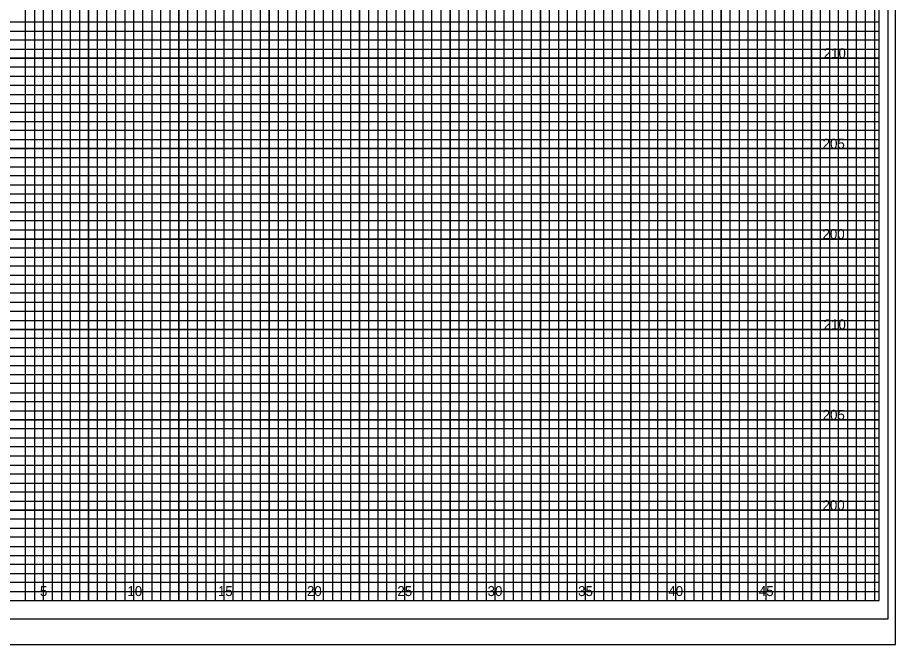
# Model space of a CAD drawing. Extents: x -4 to 103, y -2 to 209.
# Drawn here: x 54.82 to 103.4, y 68.4 to 103.08 of the extents above; entities that cross this region are included whole.
import ezdxf

# ---------------------------------------------------------------- set-up
doc = ezdxf.new("R2010")
doc.units = 0
for name, color, linetype in [('Old_Level_10', 7, 'Continuous'), ('Old_Level_16', 7, 'Continuous'), ('Old_Level_17', 7, 'Continuous'), ('Old_Level_3', 7, 'Continuous'), ('Old_Level_5', 7, 'Continuous'), ('Old_Level_6', 7, 'Continuous'), ('Old_Level_8', 7, 'Continuous'), ('Prop Dimension', 7, 'Continuous'), ('Typical Curb CELL', 7, 'Continuous')]:
    doc.layers.add(name, color=color, linetype=linetype)

msp = doc.modelspace()

# ---------------------------------------------------------------- linework, layer by layer
at = {"layer": 'Old_Level_10'}
for p, q in [((56.25, 70.825), (56.25, 135.825)), ((58.75, 70.825), (58.75, 135.825)), ((61.25, 70.825), (61.25, 135.825)), ((63.75, 70.825), (63.75, 135.825)), ((66.25, 70.825), (66.25, 135.825)), ((68.75, 70.825), (68.75, 135.825)), ((71.25, 70.825), (71.25, 135.825)), ((73.75, 70.825), (73.75, 135.825)), ((91.25, 70.825), (91.25, 134.25)), ((93.75, 70.825), (93.75, 134.25)), ((96.25, 70.825), (96.25, 134.25)), ((98.75, 70.825), (98.75, 134.25)), ((101.25, 70.825), (101.25, 134.25)), ((76.25, 70.825), (76.25, 132.825)), ((78.75, 70.825), (78.75, 132.825)), ((81.25, 70.825), (81.25, 132.825)), ((83.75, 70.825), (83.75, 132.825)), ((86.25, 70.825), (86.25, 132.825)), ((88.75, 70.825), (88.75, 132.825)), ((0, 100.825), (102.5, 100.825)), ((0, 98.325), (102.5, 98.325)), ((0, 95.825), (102.5, 95.825)), ((0, 93.325), (102.5, 93.325)), ((0, 90.825), (102.5, 90.825)), ((0, 88.325), (102.5, 88.325)), ((0, 85.825), (102.5, 85.825)), ((0, 83.325), (102.5, 83.325)), ((0, 80.825), (102.5, 80.825)), ((0, 78.325), (102.5, 78.325)), ((0, 75.825), (102.5, 75.825)), ((0, 73.325), (102.5, 73.325))]:
    msp.add_line(p, q, dxfattribs=at)
at = {"layer": 'Old_Level_17'}
for points in [[(54.75, 70.825), (55.25, 70.825), (55.25, 135.825)], [(55.75, 135.825), (55.75, 70.825), (56.75, 70.825), (56.75, 135.825)], [(57.25, 135.825), (57.25, 70.825), (57.75, 70.825), (57.75, 135.825)], [(58.25, 135.825), (58.25, 70.825), (59.25, 70.825), (59.25, 135.825)], [(59.75, 135.825), (59.75, 70.825), (60.25, 70.825), (60.25, 135.825)], [(60.75, 135.825), (60.75, 70.825), (61.75, 70.825), (61.75, 135.825)], [(62.25, 135.825), (62.25, 70.825), (62.75, 70.825), (62.75, 135.825)], [(63.25, 135.825), (63.25, 70.825), (64.25, 70.825), (64.25, 135.825)], [(64.75, 135.825), (64.75, 70.825), (65.25, 70.825), (65.25, 135.825)], [(65.75, 135.825), (65.75, 70.825), (66.75, 70.825), (66.75, 135.825)], [(67.25, 135.825), (67.25, 70.825), (67.75, 70.825), (67.75, 135.825)], [(68.25, 135.825), (68.25, 70.825), (69.25, 70.825), (69.25, 135.825)], [(69.75, 135.825), (69.75, 70.825), (70.25, 70.825), (70.25, 135.825)], [(70.75, 135.825), (70.75, 70.825), (71.75, 70.825), (71.75, 135.825)], [(72.25, 135.825), (72.25, 70.825), (72.75, 70.825), (72.75, 135.825)], [(73.25, 135.825), (73.25, 70.825), (74.25, 70.825), (74.25, 132.825)], [(89.75, 132.825), (89.75, 70.825), (90.25, 70.825), (90.25, 134.25)], [(90.75, 134.25), (90.75, 70.825), (91.75, 70.825), (91.75, 134.25)], [(92.25, 134.25), (92.25, 70.825), (92.75, 70.825), (92.75, 134.25)], [(93.25, 134.25), (93.25, 70.825), (94.25, 70.825), (94.25, 134.25)], [(94.75, 134.25), (94.75, 70.825), (95.25, 70.825), (95.25, 134.25)], [(95.75, 134.25), (95.75, 70.825), (96.75, 70.825), (96.75, 134.25)], [(97.25, 134.25), (97.25, 70.825), (97.75, 70.825), (97.75, 134.25)], [(98.25, 134.25), (98.25, 70.825), (99.25, 70.825), (99.25, 134.25)], [(99.75, 134.25), (99.75, 70.825), (100.25, 70.825), (100.25, 134.25)], [(100.25, 134.25), (100.75, 134.25), (100.75, 70.825), (101.75, 70.825), (101.75, 134.25), (102.25, 134.25), (102.25, 70.825)], [(74.75, 132.825), (74.75, 70.825), (75.25, 70.825), (75.25, 132.825)], [(75.75, 132.825), (75.75, 70.825), (76.75, 70.825), (76.75, 132.825)], [(77.25, 132.825), (77.25, 70.825), (77.75, 70.825), (77.75, 132.825)], [(78.25, 132.825), (78.25, 70.825), (79.25, 70.825), (79.25, 132.825)], [(79.75, 132.825), (79.75, 70.825), (80.25, 70.825), (80.25, 132.825)], [(80.75, 132.825), (80.75, 70.825), (81.75, 70.825), (81.75, 132.825)], [(82.25, 132.825), (82.25, 70.825), (82.75, 70.825), (82.75, 132.825)], [(83.25, 132.825), (83.25, 70.825), (84.25, 70.825), (84.25, 132.825)], [(84.75, 132.825), (84.75, 70.825), (85.25, 70.825), (85.25, 132.825)], [(85.75, 132.825), (85.75, 70.825), (86.75, 70.825), (86.75, 132.825)], [(87.25, 132.825), (87.25, 70.825), (87.75, 70.825), (87.75, 132.825)], [(88.25, 132.825), (88.25, 70.825), (89.25, 70.825), (89.25, 132.825)], [(0, 102.325), (102.5, 102.325), (102.5, 102.825), (0, 102.825)], [(0, 101.325), (102.5, 101.325), (102.5, 101.825), (0, 101.825)], [(0, 99.825), (102.5, 99.825), (102.5, 100.325), (0, 100.325)], [(0, 98.825), (102.5, 98.825), (102.5, 99.325), (0, 99.325)], [(0, 97.325), (102.5, 97.325), (102.5, 97.825), (0, 97.825)], [(0, 96.325), (102.5, 96.325), (102.5, 96.825), (0, 96.825)], [(0, 94.825), (102.5, 94.825), (102.5, 95.325), (0, 95.325)], [(0, 93.825), (102.5, 93.825), (102.5, 94.325), (0, 94.325)], [(0, 92.325), (102.5, 92.325), (102.5, 92.825), (0, 92.825)], [(0, 91.325), (102.5, 91.325), (102.5, 91.825), (0, 91.825)], [(0, 89.825), (102.5, 89.825), (102.5, 90.325), (0, 90.325)], [(0, 88.825), (102.5, 88.825), (102.5, 89.325), (0, 89.325)], [(0, 87.325), (102.5, 87.325), (102.5, 87.825), (0, 87.825)], [(0, 86.325), (102.5, 86.325), (102.5, 86.825), (0, 86.825)], [(0, 84.825), (102.5, 84.825), (102.5, 85.325), (0, 85.325)], [(0, 83.825), (102.5, 83.825), (102.5, 84.325), (0, 84.325)], [(0, 82.325), (102.5, 82.325), (102.5, 82.825), (0, 82.825)], [(0, 81.325), (102.5, 81.325), (102.5, 81.825), (0, 81.825)], [(0, 79.825), (102.5, 79.825), (102.5, 80.325), (0, 80.325)], [(0, 78.825), (102.5, 78.825), (102.5, 79.325), (0, 79.325)], [(0, 77.325), (102.5, 77.325), (102.5, 77.825), (0, 77.825)], [(0, 76.325), (102.5, 76.325), (102.5, 76.825), (0, 76.825)], [(0, 74.825), (102.5, 74.825), (102.5, 75.325), (0, 75.325)], [(0, 73.825), (102.5, 73.825), (102.5, 74.325), (0, 74.325)], [(0, 72.325), (102.5, 72.325), (102.5, 72.825), (0, 72.825)], [(0, 71.325), (102.5, 71.325), (102.5, 71.825), (0, 71.825)]]:
    msp.add_lwpolyline(points, dxfattribs=at)
at = {"layer": 'Old_Level_3'}
msp.add_line((-3.5, 68.4), (103.4, 68.4), dxfattribs=at)
at = {"layer": 'Old_Level_5'}
msp.add_lwpolyline([(103.4, 138.225), (-3.5, 138.225), (-3.5, 68.4), (103.4, 68.4)], close=True, dxfattribs=at)
at = {"layer": 'Old_Level_6'}
msp.add_lwpolyline([(102.5, 135.825), (0, 135.825), (0, 70.825), (102.5, 70.825)], close=True, dxfattribs=at)
at = {"layer": 'Old_Level_8'}
for points in [[(56.25, 70.825), (56.25, 135.825)], [(58.75, 135.825), (58.75, 70.825), (61.25, 70.825), (61.25, 135.825)], [(63.75, 135.825), (63.75, 70.825), (66.25, 70.825), (66.25, 135.825)], [(68.75, 135.825), (68.75, 70.825), (71.25, 70.825), (71.25, 135.825)], [(73.75, 135.825), (73.75, 70.825), (76.25, 70.825), (76.25, 132.825)], [(88.75, 132.825), (88.75, 70.825), (91.25, 70.825), (91.25, 134.25)], [(93.75, 134.25), (93.75, 70.825), (96.25, 70.825), (96.25, 134.25)], [(98.75, 134.25), (98.75, 70.825), (101.25, 70.825), (101.25, 134.25)], [(78.75, 132.825), (78.75, 70.825), (81.25, 70.825), (81.25, 132.825)], [(83.75, 132.825), (83.75, 70.825), (86.25, 70.825), (86.25, 132.825)], [(0, 98.325), (102.5, 98.325), (102.5, 100.825), (0, 100.825)], [(0, 93.325), (102.5, 93.325), (102.5, 95.825), (0, 95.825)], [(0, 88.325), (102.5, 88.325), (102.5, 90.825), (0, 90.825)], [(0, 83.325), (102.5, 83.325), (102.5, 85.825), (0, 85.825)], [(0, 78.325), (102.5, 78.325), (102.5, 80.825), (0, 80.825)], [(0, 73.325), (102.5, 73.325), (102.5, 75.825), (0, 75.825)]]:
    msp.add_lwpolyline(points, dxfattribs=at)
at = {"layer": 'Typical Curb CELL'}
msp.add_lwpolyline([(103, 136.825), (-2.8, 136.825), (-2.8, 69.825), (103, 69.825)], close=True, dxfattribs=at)

# ---------------------------------------------------------------- texts
at = {"layer": 'Old_Level_16'}
for s, p in [('5', (56.0574, 71.075)), ('10', (60.8971, 71.075)), ('15', (65.9057, 71.075)), ('20', (70.8312, 71.075)), ('25', (75.8399, 71.075)), ('30', (80.8312, 71.075)), ('35', (85.8399, 71.075)), ('40', (90.8313, 71.075)), ('45', (95.8399, 71.075))]:
    msp.add_text(s, height=0.55, dxfattribs=at).set_placement(p)
at = {"layer": 'Prop Dimension'}
for s, p in [('210', (99.4296, 100.825)), ('205', (99.3724, 95.825)), ('200', (99.3638, 90.825)), ('210', (99.4296, 85.825)), ('205', (99.3724, 80.825)), ('200', (99.3638, 75.825))]:
    msp.add_text(s, height=0.55, dxfattribs=at).set_placement(p)

doc.saveas('drawing.dxf')
